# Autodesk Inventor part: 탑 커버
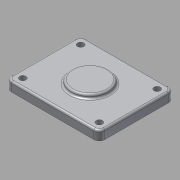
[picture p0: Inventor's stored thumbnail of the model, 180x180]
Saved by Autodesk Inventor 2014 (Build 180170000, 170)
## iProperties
Created: 2017-05
Part Number: 탑 커버
Material: 알루미늄 6061
Document SubType Name: Modeling
Designer: mduedu
Density: 1 g/cm^3
Appearance: Aluminum - Flat
Author: mduedu
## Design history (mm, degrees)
sketch "스케치1"
  geometry: L1 (25, 20)-(-25, 20); L2 (-25, 20)-(-25, -20); L3 (-25, -20)-(25, -20); L4 (25, -20)-(25, 20); L5 (25, 20)-(-25, -20); L6 (-25, 20)-(25, -20); 1 further point
  constraints: 12 end point, 2 midpoint, 2 parallel, 1 horizontal, 1 perpendicular
  dimensions: "d0" = 50 distance of L3.end L2.end; "d1" = 40 distance of L2.end L1.end
extrude "돌출1" new body sketch "스케치1" distance "d2" = 5; taper "d3" = 0 deg
fillet "모깎기1" dims "d4" = 3
sketch "스케치2"
  geometry: C1 r 10 at (0, 0); 1 further point
  constraints: 1 centre point, 1 coincident
  dimensions: "d5" = 20 diameter of C1
extrude "돌출2" join sketch "스케치2" distance "d6" = 2; taper "d7" = 0 deg
sketch "스케치3"
  geometry: L1 (-16, -11)-(16, -11); L2 (16, -11)-(16, 11); L3 (16, 11)-(-16, 11); L4 (-16, 11)-(-16, -11); L5 (-16, -11)-(16, 11); L6 (16, -11)-(-16, 11); 1 further point
  constraints: 12 end point, 2 midpoint, 2 parallel, 1 horizontal, 1 perpendicular
  dimensions: "d8" = 32 distance of L3.end L2.end; "d9" = 22 distance of L2.end L1.end
extrude "돌출3" join sketch "스케치3" distance "d10" = 3; taper "d11" = 0 deg
fillet "모깎기2" dims "d12" = 3
sketch "스케치4"
  geometry: L1 (-13, -11)-(13, -11) reference; L2 (16, -8)-(16, 8) reference; L3 (13, 11)-(-13, 11) reference; L4 (-16, 8)-(-16, -8) reference; L5 (-13, 9)-(13, 9); L6 (14, 8)-(14, -8); L7 (13, -9)-(-13, -9); L8 (-14, -8)-(-14, 8); A1 r 3 centre (-13, -8) between (-16, -8) and (-13, -11) reference; A2 r 3 centre (13, -8) between (13, -11) and (16, -8) reference; A3 r 3 centre (13, 8) between (16, 8) and (13, 11) reference; A4 r 3 centre (-13, 8) between (-13, 11) and (-16, 8) reference; A5 r 1 centre (13, 8) between (14, 8) and (13, 9); A6 r 1 centre (13, -8) between (13, -9) and (14, -8); A7 r 1 centre (-13, -8) between (-14, -8) and (-13, -9); A8 r 1 centre (-13, 8) between (-13, 9) and (-14, 8); 1 further point
  constraints: 8 end point, 8 point on circle, 4 centre point, 7 other
  dimensions: "d13" = 2 distance between parallel lines of L5 L3
extrude "돌출4" cut sketch "스케치4" stored distance "d14" = 2; taper "d15" = 0 deg
chamfer "모따기1" distance "d16" = 1; stored, may be unused: second distance "d17" = 2, angle "d18" = 45 deg
fillet "모깎기3" dims "d19" = 1
fillet "모깎기4" dims "d20" = 1
fillet "모깎기5" dims "d21" = 1
sketch "스케치5"
  geometry: L1 (-20.5, -15.5)-(20.5, -15.5); L2 (20.5, -15.5)-(20.5, 15.5); L3 (20.5, 15.5)-(-20.5, 15.5); L4 (-20.5, 15.5)-(-20.5, -15.5); L5 (-20.5, -15.5)-(20.5, 15.5); L6 (20.5, -15.5)-(-20.5, 15.5); L7 (22, 20)-(-22, 20) reference; L8 (25, -17)-(25, 17) reference; 5 further points
  constraints: 12 end point, 4 coincident, 2 midpoint, 2 parallel, 1 horizontal, 1 perpendicular
  dimensions: "d22" = 4.5 distance between parallel lines of L3 L7; "d23" = 4.5 distance between parallel lines of L2 L8
sketch "스케치6"
  geometry: 4 further points
  constraints: 4 other
hole "구멍1" sketch "스케치6" at (-20.5, 15.5), (20.5, 15.5), (20.5, -15.5), (-20.5, -15.5) diameter "d24" = 3.4; stored, may be unused: countersink angle "d28" = 90 deg, drill point angle "d30" = 0 deg; dims "d25" = 6, "d26" = 4, "d27" = 2, "d29" = 8
node "솔리드1"
node "투영된 루프1"
